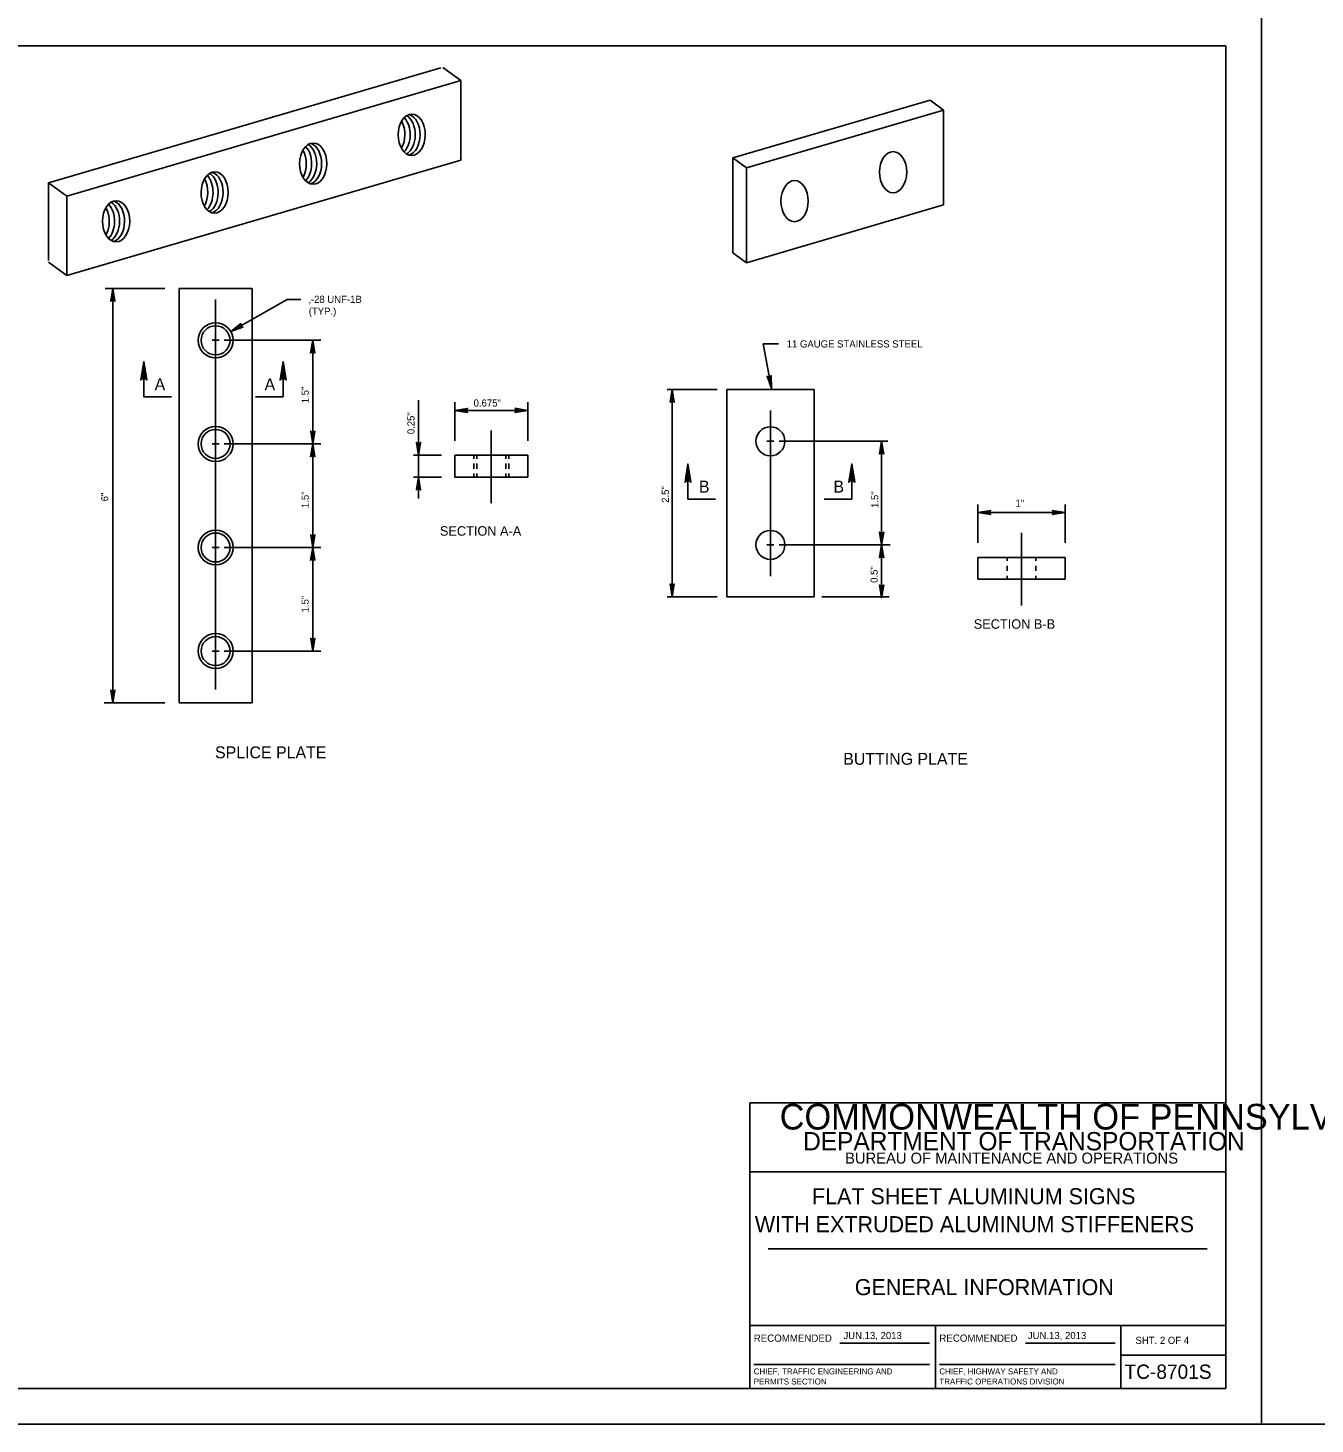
# Model space of a CAD drawing. Extents: x 650495 to 652241, y 298458 to 299646.
# Drawn here: x 650818 to 651359, y 298458 to 299044 of the extents above; entities that cross this region are included whole.
import ezdxf

# ---------------------------------------------------------------- set-up
doc = ezdxf.new("R2010")
doc.units = 0
for name, color, linetype in [('1', 7, 'Continuous'), ('2', 7, 'Continuous'), ('PLT-BNDY', 7, 'Continuous')]:
    doc.layers.add(name, color=color, linetype=linetype)

msp = doc.modelspace()

# ---------------------------------------------------------------- linework, layer by layer
at = {"layer": '1'}
for p, q in [((650535.31, 299036.63), (651321.31, 299036.63)), ((651321.31, 298472.63), (651321.31, 299036.63)), ((651121.31, 298472.63), (651121.31, 298592.63)), ((651121.31, 298592.63), (651321.31, 298592.63)), ((651321.31, 298563.63), (651121.31, 298563.63)), ((651129.06, 298531.31), (651313.56, 298531.31)), ((651121.31, 298499), (651321.31, 298499)), ((651199.31, 298499), (651199.31, 298472.63)), ((651277.19, 298472.63), (651277.19, 298499)), ((651159.24, 298491.57), (651196.87, 298491.57)), ((651237.24, 298491.57), (651274.87, 298491.57)), ((651122.99, 298482.68), (651196.87, 298482.68)), ((651200.99, 298482.68), (651274.87, 298482.68)), ((651277.19, 298486.63), (651321.31, 298486.63)), ((651321.31, 298472.63), (650535.31, 298472.63)), ((650535.31, 298472.63), (651121.31, 298472.63))]:
    msp.add_line(p, q, dxfattribs=at)
at = {"layer": '2'}
for p, q in [((650826.67, 298979.09), (650991.56, 299027.33)), ((650992.3, 299027.55), (650999.99, 299021.97)), ((650834.39, 298973.52), (650999.99, 299021.97)), ((650999.99, 298988.58), (650999.99, 299021.97)), ((651114.2, 298989.49), (651197.08, 299013.73)), ((651119.92, 298985.41), (651202.72, 299009.64)), ((651197.08, 299013.73), (651202.72, 299009.64)), ((651202.72, 298969.74), (651202.72, 299009.64)), ((650834.39, 298940.12), (650999.99, 298988.58)), ((651114.2, 298989.56), (651119.92, 298985.41)), ((651114.2, 298949.66), (651114.2, 298989.56)), ((651119.92, 298945.51), (651119.92, 298985.41)), ((650826.67, 298946.44), (650826.67, 298979.09)), ((650826.69, 298979.09), (650834.39, 298973.52)), ((650834.39, 298940.12), (650834.39, 298973.52)), ((651119.92, 298945.51), (651202.72, 298969.74)), ((650826.67, 298945.72), (650834.39, 298940.12)), ((651114.2, 298949.66), (651119.92, 298945.51)), ((650850.56, 298934.65), (650875.54, 298934.65)), ((650853.71, 298760.59), (650853.71, 298934.65)), ((650881.57, 298934.65), (650912.22, 298934.65)), ((650881.57, 298760.59), (650881.57, 298934.65)), ((650912.22, 298760.59), (650912.22, 298934.65)), ((650896.9, 298766.22), (650896.9, 298930.04)), ((650926.97, 298930.1), (650903.27, 298916.54)), ((650926.97, 298930.1), (650932.73, 298930.1)), ((650895.38, 298912.89), (650898.35, 298912.89)), ((650900.54, 298912.89), (650941.08, 298912.89)), ((650937.69, 298869.38), (650937.69, 298912.89)), ((651126.94, 298911.46), (651133.46, 298911.46)), ((651126.94, 298911.46), (651130.47, 298892.65)), ((650866.76, 298889.13), (650866.76, 298903.94)), ((650925.24, 298889.13), (650925.24, 298903.94)), ((651086.58, 298892.22), (651107.57, 298892.22)), ((651088.75, 298805.19), (651088.75, 298892.22)), ((651111.68, 298805.19), (651111.68, 298892.22)), ((651111.68, 298892.22), (651148.32, 298892.22)), ((651148.32, 298805.19), (651148.32, 298892.22)), ((650866.76, 298889.13), (650878.34, 298889.13)), ((650925.24, 298889.13), (650913.65, 298889.13)), ((650982.14, 298864.61), (650982.14, 298887.79)), ((650997.4, 298870.71), (650997.4, 298886.88)), ((651028.05, 298870.71), (651028.05, 298886.88)), ((650997.4, 298883.47), (651028.05, 298883.47)), ((651130, 298813.85), (651130, 298883.44)), ((651012.73, 298844.49), (651012.73, 298875.01)), ((650895.38, 298869.38), (650898.35, 298869.38)), ((650900.54, 298869.38), (650941.08, 298869.38)), ((650937.69, 298825.86), (650937.69, 298869.38)), ((651128.48, 298870.47), (651131.45, 298870.47)), ((651133.64, 298870.47), (651179.4, 298870.47)), ((651176.75, 298826.95), (651176.75, 298870.47)), ((650980.02, 298864.61), (650991.76, 298864.61)), ((650982.14, 298855.45), (650982.14, 298864.61)), ((650997.4, 298864.61), (651028.05, 298864.61)), ((650997.4, 298855.45), (650997.4, 298864.61)), ((651005.38, 298863.17), (651005.38, 298864.61)), ((651006.64, 298863.17), (651006.64, 298864.61)), ((651018.81, 298863.17), (651018.81, 298864.61)), ((651020.07, 298863.17), (651020.07, 298864.61)), ((651028.05, 298855.45), (651028.05, 298864.61)), ((651005.38, 298858.96), (651005.38, 298861.15)), ((651006.64, 298858.96), (651006.64, 298861.15)), ((651018.81, 298858.96), (651018.81, 298861.15)), ((651020.07, 298858.96), (651020.07, 298861.15)), ((651095.37, 298846.19), (651095.37, 298860.99)), ((651164.18, 298846.19), (651164.18, 298860.99)), ((650980.02, 298855.45), (650991.76, 298855.45)), ((650982.14, 298846.51), (650982.14, 298855.45)), ((650997.4, 298855.45), (651028.05, 298855.45)), ((651005.38, 298855.45), (651005.38, 298856.89)), ((651006.64, 298855.45), (651006.64, 298856.89)), ((651018.81, 298855.45), (651018.81, 298856.89)), ((651020.07, 298855.45), (651020.07, 298856.89)), ((651095.37, 298846.19), (651106.96, 298846.19)), ((651164.18, 298846.19), (651152.59, 298846.19)), ((651217.18, 298827.77), (651217.18, 298843.93)), ((651217.18, 298840.53), (651253.82, 298840.53)), ((651253.82, 298827.77), (651253.82, 298843.93)), ((651235.5, 298801.54), (651235.5, 298832.07)), ((650895.38, 298825.86), (650898.35, 298825.86)), ((650900.54, 298825.86), (650941.08, 298825.86)), ((650937.69, 298782.35), (650937.69, 298825.86)), ((651128.48, 298826.95), (651131.45, 298826.95)), ((651133.64, 298826.95), (651180.3, 298826.95)), ((651176.75, 298804.74), (651176.75, 298826.95)), ((651217.18, 298821.67), (651253.82, 298821.67)), ((651217.18, 298812.51), (651217.18, 298821.67)), ((651229.42, 298820.23), (651229.42, 298821.67)), ((651229.42, 298816.02), (651229.42, 298818.21)), ((651241.59, 298820.23), (651241.59, 298821.67)), ((651241.59, 298816.02), (651241.59, 298818.21)), ((651253.82, 298812.51), (651253.82, 298821.67)), ((651217.18, 298812.51), (651253.82, 298812.51)), ((651229.42, 298812.51), (651229.42, 298813.95)), ((651241.59, 298812.51), (651241.59, 298813.95)), ((651086.58, 298805.19), (651107.57, 298805.19)), ((651111.68, 298805.19), (651148.32, 298805.19)), ((651179.85, 298805.19), (651151.63, 298805.19)), ((650895.38, 298782.35), (650898.35, 298782.35)), ((650900.54, 298782.35), (650941.08, 298782.35)), ((650850.12, 298760.59), (650875.54, 298760.59)), ((650881.57, 298760.59), (650912.22, 298760.59))]:
    msp.add_line(p, q, dxfattribs=at)
for points in [[(650853.07, 298929.54), (650853.44, 298929.73), (650853.71, 298934.65), (650853.07, 298929.54), (650852.84, 298929.28), (650853.71, 298934.65), (650853.95, 298929.74), (650854.32, 298929.56), (650853.71, 298934.65), (650854.56, 298929.28), (650854.32, 298929.56)], [(650908.02, 298918.52), (650907.67, 298918.75), (650903.27, 298916.54), (650908.02, 298918.52), (650908.36, 298918.45), (650903.27, 298916.54), (650907.41, 298919.19), (650907.39, 298919.6), (650903.27, 298916.54), (650907.51, 298919.95), (650907.39, 298919.6)], [(650937.05, 298907.78), (650937.42, 298907.97), (650937.69, 298912.89), (650937.05, 298907.78), (650936.83, 298907.52), (650937.69, 298912.89), (650937.94, 298907.98), (650938.3, 298907.8), (650937.69, 298912.89), (650938.55, 298907.52), (650938.3, 298907.8)], [(650865.84, 298896.58), (650866.37, 298896.85), (650866.76, 298903.94), (650865.84, 298896.58), (650865.51, 298896.2), (650866.76, 298903.94), (650867.11, 298896.86), (650867.64, 298896.6), (650866.76, 298903.94), (650867.99, 298896.2), (650867.64, 298896.6)], [(650926.16, 298896.58), (650925.63, 298896.85), (650925.24, 298903.94), (650926.16, 298896.58), (650926.49, 298896.2), (650925.24, 298903.94), (650924.89, 298896.86), (650924.36, 298896.6), (650925.24, 298903.94), (650924.01, 298896.2), (650924.36, 298896.6)], [(651130.16, 298897.78), (651129.83, 298897.53), (651130.47, 298892.65), (651130.16, 298897.78), (651130.33, 298898.08), (651130.47, 298892.65), (651129.32, 298897.43), (651128.93, 298897.54), (651130.47, 298892.65), (651128.64, 298897.77), (651128.93, 298897.54)], [(651088.11, 298887.11), (651088.48, 298887.3), (651088.75, 298892.22), (651088.11, 298887.11), (651087.89, 298886.85), (651088.75, 298892.22), (651088.99, 298887.31), (651089.36, 298887.13), (651088.75, 298892.22), (651089.61, 298886.85), (651089.36, 298887.13)], [(651002.51, 298882.83), (651002.32, 298883.2), (650997.4, 298883.47), (651002.51, 298882.83), (651002.77, 298882.6), (650997.4, 298883.47), (651002.32, 298883.71), (651002.5, 298884.08), (650997.4, 298883.47), (651002.77, 298884.32), (651002.5, 298884.08)], [(651022.94, 298884.11), (651023.13, 298883.74), (651028.05, 298883.47), (651022.94, 298884.11), (651022.68, 298884.33), (651028.05, 298883.47), (651023.14, 298883.23), (651022.96, 298882.86), (651028.05, 298883.47), (651022.68, 298882.62), (651022.96, 298882.86)], [(650938.33, 298874.49), (650937.97, 298874.3), (650937.69, 298869.38), (650938.33, 298874.49), (650938.56, 298874.75), (650937.69, 298869.38), (650937.45, 298874.29), (650937.08, 298874.47), (650937.69, 298869.38), (650936.84, 298874.75), (650937.08, 298874.47)], [(650937.05, 298864.27), (650937.42, 298864.46), (650937.69, 298869.38), (650937.05, 298864.27), (650936.83, 298864.01), (650937.69, 298869.38), (650937.94, 298864.46), (650938.3, 298864.28), (650937.69, 298869.38), (650938.55, 298864.01), (650938.3, 298864.28)], [(650982.78, 298869.72), (650982.41, 298869.53), (650982.14, 298864.61), (650982.78, 298869.72), (650983.01, 298869.98), (650982.14, 298864.61), (650981.9, 298869.53), (650981.53, 298869.71), (650982.14, 298864.61), (650981.29, 298869.98), (650981.53, 298869.71)], [(651176.11, 298865.36), (651176.48, 298865.55), (651176.75, 298870.47), (651176.11, 298865.36), (651175.88, 298865.1), (651176.75, 298870.47), (651176.99, 298865.55), (651177.36, 298865.37), (651176.75, 298870.47), (651177.6, 298865.1), (651177.36, 298865.37)], [(651094.45, 298853.64), (651094.98, 298853.91), (651095.37, 298860.99), (651094.45, 298853.64), (651094.12, 298853.26), (651095.37, 298860.99), (651095.72, 298853.92), (651096.25, 298853.66), (651095.37, 298860.99), (651096.6, 298853.26), (651096.25, 298853.66)], [(651165.1, 298853.64), (651164.57, 298853.91), (651164.18, 298860.99), (651165.1, 298853.64), (651165.42, 298853.26), (651164.18, 298860.99), (651163.83, 298853.92), (651163.3, 298853.66), (651164.18, 298860.99), (651162.95, 298853.26), (651163.3, 298853.66)], [(650981.5, 298850.34), (650981.87, 298850.53), (650982.14, 298855.45), (650981.5, 298850.34), (650981.27, 298850.08), (650982.14, 298855.45), (650982.38, 298850.54), (650982.75, 298850.36), (650982.14, 298855.45), (650982.99, 298850.08), (650982.75, 298850.36)], [(651222.29, 298839.88), (651222.1, 298840.25), (651217.18, 298840.53), (651222.29, 298839.88), (651222.55, 298839.66), (651217.18, 298840.53), (651222.09, 298840.77), (651222.27, 298841.14), (651217.18, 298840.53), (651222.55, 298841.38), (651222.27, 298841.14)], [(651248.72, 298841.17), (651248.91, 298840.8), (651253.82, 298840.53), (651248.72, 298841.17), (651248.45, 298841.39), (651253.82, 298840.53), (651248.91, 298840.28), (651248.73, 298839.92), (651253.82, 298840.53), (651248.45, 298839.67), (651248.73, 298839.92)], [(650938.33, 298830.97), (650937.97, 298830.78), (650937.69, 298825.86), (650938.33, 298830.97), (650938.56, 298831.23), (650937.69, 298825.86), (650937.45, 298830.78), (650937.08, 298830.96), (650937.69, 298825.86), (650936.84, 298831.23), (650937.08, 298830.96)], [(651177.39, 298832.06), (651177.02, 298831.87), (651176.75, 298826.95), (651177.39, 298832.06), (651177.61, 298832.32), (651176.75, 298826.95), (651176.5, 298831.86), (651176.14, 298832.04), (651176.75, 298826.95), (651175.89, 298832.32), (651176.14, 298832.04)], [(650937.05, 298820.75), (650937.42, 298820.94), (650937.69, 298825.86), (650937.05, 298820.75), (650936.83, 298820.49), (650937.69, 298825.86), (650937.94, 298820.95), (650938.3, 298820.77), (650937.69, 298825.86), (650938.55, 298820.49), (650938.3, 298820.77)], [(651176.11, 298821.84), (651176.48, 298822.03), (651176.75, 298826.95), (651176.11, 298821.84), (651175.88, 298821.58), (651176.75, 298826.95), (651176.99, 298822.04), (651177.36, 298821.86), (651176.75, 298826.95), (651177.6, 298821.58), (651177.36, 298821.86)], [(651089.39, 298810.3), (651089.02, 298810.11), (651088.75, 298805.19), (651089.39, 298810.3), (651089.62, 298810.56), (651088.75, 298805.19), (651088.51, 298810.11), (651088.14, 298810.29), (651088.75, 298805.19), (651087.9, 298810.56), (651088.14, 298810.29)], [(651177.39, 298809.85), (651177.02, 298809.66), (651176.75, 298804.74), (651177.39, 298809.85), (651177.61, 298810.11), (651176.75, 298804.74), (651176.5, 298809.66), (651176.14, 298809.84), (651176.75, 298804.74), (651175.89, 298810.11), (651176.14, 298809.84)], [(650938.33, 298787.46), (650937.97, 298787.27), (650937.69, 298782.35), (650938.33, 298787.46), (650938.56, 298787.72), (650937.69, 298782.35), (650937.45, 298787.26), (650937.08, 298787.44), (650937.69, 298782.35), (650936.84, 298787.72), (650937.08, 298787.44)], [(650854.35, 298765.7), (650853.98, 298765.51), (650853.71, 298760.59), (650854.35, 298765.7), (650854.57, 298765.96), (650853.71, 298760.59), (650853.46, 298765.5), (650853.1, 298765.68), (650853.71, 298760.59), (650852.85, 298765.96), (650853.1, 298765.68)]]:
    msp.add_lwpolyline(points, dxfattribs=at)
for centre, radius in [((650896.9, 298912.89), 7.34), ((650896.9, 298912.89), 6.09), ((650896.9, 298869.38), 7.34), ((650896.9, 298869.38), 6.09), ((651130, 298870.47), 6.09), ((650896.9, 298825.86), 7.34), ((650896.9, 298825.86), 6.09), ((651130, 298826.95), 6.09), ((650896.9, 298782.35), 7.34), ((650896.9, 298782.35), 6.09)]:
    msp.add_circle(centre, radius, dxfattribs=at)
for centre in [(650979.29, 298999.22), (650937.89, 298987.11), (651181.56, 298983.5), (650896.49, 298974.99), (651140.16, 298971.38), (650855.09, 298962.88)]:
    msp.add_ellipse(centre, major_axis=(0.05, 8.67), ratio=0.658454, dxfattribs=at)
for centre, start_param, end_param in [((650970.71, 298999.22), 4.009549, 5.408338), ((650972.93, 298999.22), 3.741593, 5.67105), ((650975.05, 298999.22), 3.535802, 5.876738), ((650977.12, 298999.22), 3.354344, 6.055413), ((650929.3, 298987.11), 4.009549, 5.408338), ((650931.53, 298987.11), 3.741593, 5.67105), ((650933.65, 298987.11), 3.535802, 5.876738), ((650935.72, 298987.11), 3.354344, 6.055413), ((650887.9, 298974.99), 4.009549, 5.408338), ((650890.12, 298974.99), 3.741593, 5.67105), ((650892.25, 298974.99), 3.535802, 5.876738), ((650894.32, 298974.99), 3.354344, 6.055413), ((650846.5, 298962.88), 4.009549, 5.408338), ((650848.72, 298962.88), 3.741593, 5.67105), ((650850.84, 298962.88), 3.535802, 5.876738), ((650852.92, 298962.88), 3.354344, 6.055413)]:
    msp.add_ellipse(centre, major_axis=(0.05, 8.67), ratio=0.658454, start_param=start_param, end_param=end_param, dxfattribs=at)
at = {"layer": 'PLT-BNDY'}
for points in [[(650495.31, 299051.63), (651336.31, 299051.63), (651336.31, 298457.63), (650495.31, 298457.63)], [(651336.31, 299051.63), (652177.31, 299051.63), (652177.31, 298457.63), (651336.31, 298457.63)]]:
    msp.add_lwpolyline(points, close=True, dxfattribs=at)

# ---------------------------------------------------------------- texts
at = {"layer": '1'}
for s, height, p in [('COMMONWEALTH OF PENNSYLVANIA', 10.7828, (651133.9, 298581.36)), ('DEPARTMENT OF TRANSPORTATION', 7.6837, (651143.76, 298572.61)), ('BUREAU OF MAINTENANCE AND OPERATIONS', 4.6253, (651161.41, 298567.04)), ('FLAT SHEET ALUMINUM SIGNS', 6.75, (651147.47, 298549.97)), ('WITH EXTRUDED ALUMINUM STIFFENERS', 6.75, (651123.47, 298538.22)), ('GENERAL INFORMATION', 6.75, (651165.45, 298511.78)), ('RECOMMENDED', 3.048, (651122.99, 298492.2)), ('RECOMMENDED', 3.048, (651200.99, 298492.2)), ('SHT. 2 OF 4', 3, (651283.4, 298491.31)), ('TC-8701S', 6, (651278.79, 298476.63)), ('CHIEF, TRAFFIC ENGINEERING AND', 2.5, (651122.99, 298478.51)), ('PERMITS SECTION', 2.5, (651122.99, 298474.26)), ('TRAFFIC OPERATIONS DIVISION', 2.5, (651200.99, 298474.26)), ('CHIEF, HIGHWAY SAFETY AND', 2.5, (651200.99, 298478.51))]:
    msp.add_text(s, height=height, dxfattribs=at).set_placement(p)
at = {"layer": '2'}
for s, height, p in [('‚-28 UNF-1B', 3, (650936.02, 298928.62)), ('(TYP.)', 3, (650936.02, 298923.62)), ('11 GAUGE STAINLESS STEEL', 3, (651136.84, 298909.88)), ('A', 5, (650917.46, 298891.9)), ('0.675"', 3, (651005.3, 298885.07)), ('B', 5, (651099.96, 298848.95)), ('B', 5, (651156.48, 298848.95)), ('1"', 3, (651233, 298842.97)), ('SECTION A-A', 4, (650991.15, 298830.81)), ('SECTION B-B', 4, (651215.44, 298791.72)), ('SPLICE PLATE', 5, (650896.65, 298737.3)), ('BUTTING PLATE', 5, (651160.6, 298734.59)), ('JUN.13, 2013', 3, (651160.69, 298493.34)), ('JUN.13, 2013', 3, (651238.17, 298493.34))]:
    msp.add_text(s, height=height, dxfattribs=at).set_placement(p)
for s, height, rotation, p in [('A', 5, 360, (650871.27, 298891.9)), ('1.5"', 3, 90, (650936.02, 298886.44)), ('0.25"', 3, 90, (650980.47, 298873.45)), ('2.5"', 3, 90, (651087.36, 298844.6)), ('6"', 3, 90, (650851.79, 298845.25)), ('1.5"', 3, 90, (650936.02, 298842.42)), ('1.5"', 3, 90, (651175.35, 298842.44)), ('0.5"', 3, 90, (651175.07, 298810.99)), ('1.5"', 3, 90, (650936.02, 298798.58))]:
    msp.add_text(s, height=height, rotation=rotation, dxfattribs=at).set_placement(p)

doc.saveas('drawing.dxf')
